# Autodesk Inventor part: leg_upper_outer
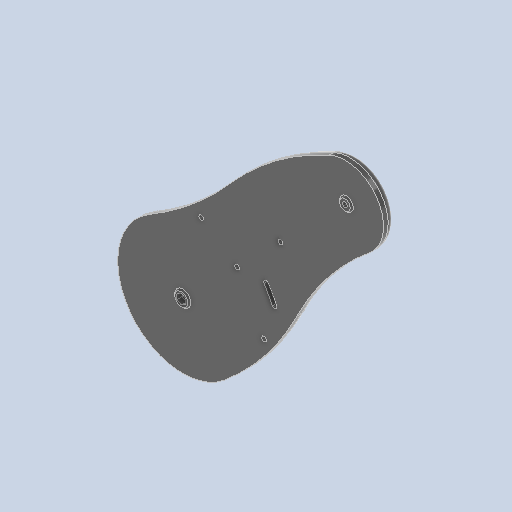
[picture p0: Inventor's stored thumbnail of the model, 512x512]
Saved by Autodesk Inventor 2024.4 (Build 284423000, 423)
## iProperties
Created: 2026-01
Part Number: leg_upper_outer
Material: Generic
Document SubType Name: Modeling
Designer: AdminForWorker
Density: 1 g/cm^3
Appearance: Default
Title: leg_upper_outer
Author: AdminForWorker
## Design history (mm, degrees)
feature "Body2"
body "Solid1"
